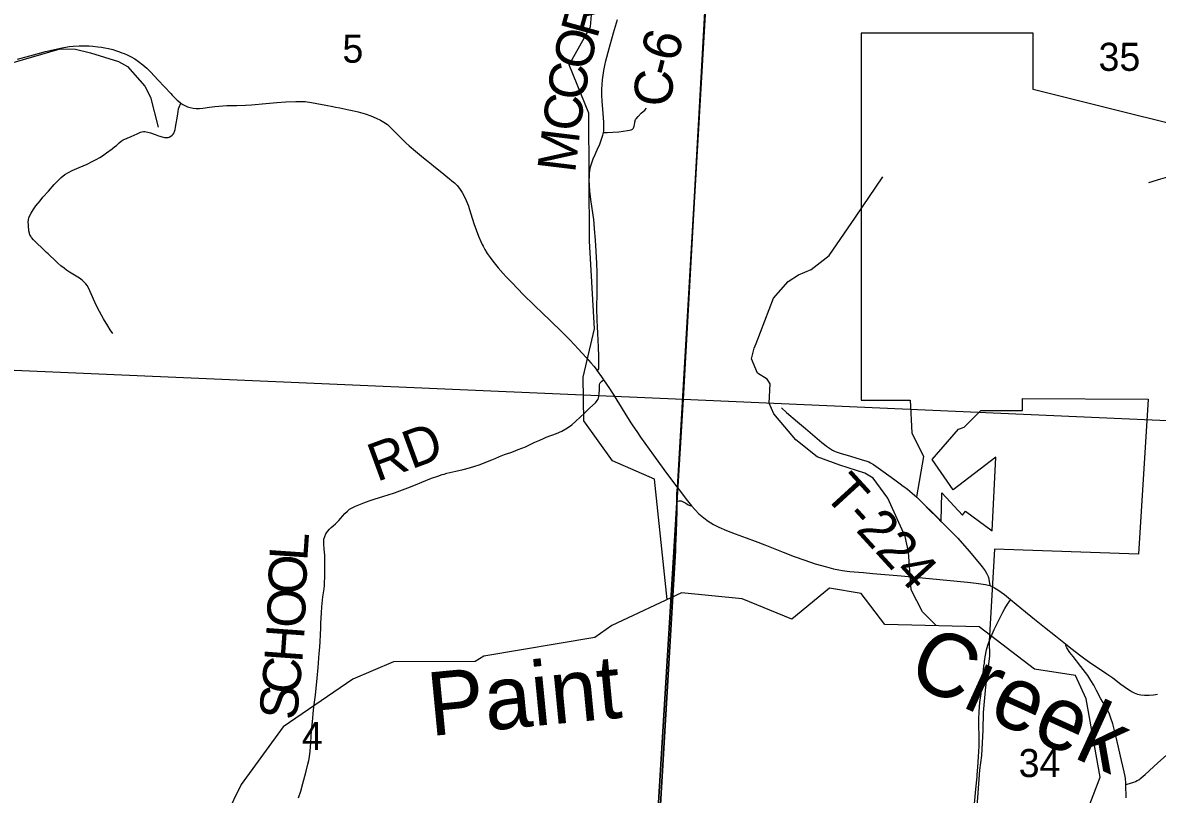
# Model space of a CAD drawing. Extents: x 0 to 34, y 0 to 22.
# Drawn here: x 5.267 to 6.959, y 19.422 to 20.572 of the extents above; entities that cross this region are included whole.
import ezdxf

# ---------------------------------------------------------------- set-up
doc = ezdxf.new("R2010")
doc.units = 0
for name, color, linetype in [('Default', 7, 'Continuous'), ('GM_X_City_Street', 7, 'Continuous'), ('GM_X_County_Road', 7, 'Continuous'), ('GM_X_County_Road_Text', 7, 'Continuous'), ('GM_X_Minor_River', 7, 'Continuous'), ('GM_X_Minor_River_Text', 7, 'Continuous'), ('GM_X_Section', 7, 'Continuous'), ('GM_X_Section_Text', 7, 'Continuous'), ('GM_X_State_Route', 7, 'Continuous'), ('GM_X_Township_Road', 7, 'Continuous'), ('GM_X_Township_Road_Text', 7, 'Continuous')]:
    doc.layers.add(name, color=color, linetype=linetype)

msp = doc.modelspace()

# ---------------------------------------------------------------- linework, layer by layer
at = {"layer": 'Default'}
for points in [[(6.0603, 16.8624), (6.127, 17.9511), (6.1612, 18.4732), (6.1665, 18.5542), (6.1773, 18.7192), (6.1898, 18.9313), (6.195, 19.011), (6.2406, 19.7849), (6.241, 19.7927), (6.2413, 19.8018), (6.2418, 19.8127), (6.2424, 19.8289), (6.2426, 19.8432), (6.2426, 19.8474), (6.2427, 19.8586), (6.2428, 19.8591), (6.2428, 19.8627), (6.2428, 19.867), (6.2428, 19.8705), (6.2431, 19.8748), (6.2438, 19.8792), (6.3032, 20.9), (2.1, 20.9), (2.1, 16.1239)], [(8.9, 20.9), (6.3032, 20.9), (6.2438, 19.8792), (6.2431, 19.8748), (6.2428, 19.8705), (6.2428, 19.867), (6.2428, 19.8627), (6.2428, 19.8591), (6.2427, 19.8586), (6.2426, 19.8474), (6.2426, 19.8432), (6.2424, 19.8289), (6.2418, 19.8127), (6.2413, 19.8018), (6.241, 19.7927), (6.2406, 19.7849), (6.195, 19.011), (6.1898, 18.9313), (6.1773, 18.7192), (6.1665, 18.5542), (6.1612, 18.4732), (6.127, 17.9511), (6.0603, 16.8624)], [(7.1065, 20.3898), (6.7739, 20.4727), (6.7739, 20.5566), (6.5176, 20.5566), (6.5176, 20.0093), (6.5907, 20.0093), (6.5933, 19.9608), (6.6104, 19.9252), (6.6004, 19.8655), (6.6369, 19.8288), (6.6379, 19.8713), (6.6688, 19.8381), (6.6733, 19.8438), (6.7128, 19.8147), (6.7182, 19.9243), (6.6546, 19.8757), (6.6236, 19.9208), (6.663, 19.9661), (6.6711, 19.9691), (6.6961, 19.9941), (6.7582, 19.9941), (6.7582, 20.0121), (6.9455, 20.011), (6.9314, 19.7799), (6.7164, 19.7873), (6.7084, 19.6502), (6.7092, 19.6275), (6.7029, 19.5821), (6.6998, 19.5435), (6.6993, 19.5175), (6.6972, 19.4796), (6.694, 19.4577), (6.6895, 19.3966)]]:
    msp.add_lwpolyline(points, dxfattribs=at)
for points in [[(6.302, 20.9), (5.259, 20.9), (5.2086, 20.056), (6.2522, 20.0112)], [(7.3433, 20.9), (6.302, 20.9), (6.2522, 20.0112), (7.2788, 19.9659)]]:
    msp.add_lwpolyline(points, close=True, dxfattribs=at)
at = {"layer": 'GM_X_City_Street'}
msp.add_lwpolyline([(6.9125, 19.4362), (6.9142, 19.4368), (6.9242, 19.4399), (6.9266, 19.4408), (6.9291, 19.442), (6.9315, 19.4434), (6.935, 19.4462), (6.941, 19.4511), (6.9598, 19.4685), (6.973, 19.4798), (6.9863, 19.4914), (6.9988, 19.5023), (7.0056, 19.5084), (7.0158, 19.5178), (7.0229, 19.5243), (7.0354, 19.5355), (7.0439, 19.5432), (7.0694, 19.5663), (7.0777, 19.5738), (7.0967, 19.5917), (7.1058, 19.6007), (7.1078, 19.6031), (7.1091, 19.6053), (7.1104, 19.6082)], dxfattribs=at)
at = {"layer": 'GM_X_County_Road'}
for points in [[(6.124, 20.0534), (6.1255, 20.0547), (6.1264, 20.0562), (6.1267, 20.0581), (6.1267, 20.0619), (6.1266, 20.0744), (6.1262, 20.0889), (6.1252, 20.1088), (6.1246, 20.1194), (6.1242, 20.1283), (6.1237, 20.147), (6.1238, 20.169), (6.1238, 20.1853), (6.1238, 20.2006), (6.1233, 20.2131), (6.1224, 20.2319), (6.1214, 20.248), (6.1201, 20.2648), (6.1196, 20.2723), (6.1188, 20.279), (6.1152, 20.3054), (6.1133, 20.3209), (6.1125, 20.3306), (6.1122, 20.3374), (6.1124, 20.3425), (6.1127, 20.3473), (6.1132, 20.3515), (6.1137, 20.3547), (6.1143, 20.3575), (6.115, 20.3605), (6.1159, 20.3634), (6.1179, 20.3693), (6.121, 20.3761), (6.1242, 20.3829), (6.1278, 20.3913), (6.1306, 20.3989), (6.1325, 20.4049), (6.1333, 20.4086), (6.1337, 20.4109), (6.1338, 20.4136), (6.1339, 20.4189), (6.1337, 20.4243), (6.1328, 20.4369), (6.1313, 20.4556), (6.1309, 20.4643), (6.1309, 20.4731), (6.1314, 20.4804), (6.1319, 20.4874), (6.1327, 20.4943), (6.1338, 20.5009), (6.1354, 20.5085), (6.1371, 20.5157), (6.1419, 20.5341), (6.1484, 20.5572), (6.1543, 20.5772)], [(6.913, 19.4164), (6.9125, 19.4362), (6.9125, 19.4378), (6.9116, 19.4459), (6.911, 19.4506), (6.91, 19.4551), (6.9056, 19.4721), (6.8992, 19.5002), (6.8953, 19.5167), (6.8927, 19.5267), (6.89, 19.5352), (6.8878, 19.5412), (6.8858, 19.5458), (6.88, 19.5559), (6.875, 19.5642), (6.8685, 19.5766), (6.8645, 19.5845), (6.8603, 19.5914), (6.8555, 19.5986), (6.8522, 19.6031), (6.8452, 19.6122), (6.8338, 19.627), (6.8289, 19.6332), (6.8242, 19.6401), (6.8233, 19.6421), (6.8226, 19.644), (6.8223, 19.6462)]]:
    msp.add_lwpolyline(points, dxfattribs=at)
at = {"layer": 'GM_X_Minor_River'}
for points in [[(6.2282, 19.712), (6.2097, 19.8916), (6.1471, 19.9191), (6.1042, 19.9787), (6.1033, 20.0436), (6.1202, 20.1158), (6.1124, 20.2467), (6.1114, 20.4376), (6.0824, 20.5098), (6.1139, 20.5663), (6.1185, 20.6206)], [(4.8862, 20.5519), (5.0445, 20.4475), (5.0679, 20.4257), (5.0873, 20.4221), (5.126, 20.4256), (5.1626, 20.4393), (5.1909, 20.456), (5.2212, 20.4928), (5.2532, 20.5133), (5.3235, 20.5335), (5.3459, 20.533), (5.3683, 20.5276), (5.4102, 20.5147), (5.4236, 20.5069), (5.4497, 20.4779), (5.4578, 20.4616), (5.4693, 20.4165)], [(6.6293, 19.6732), (6.6091, 19.6937), (6.5924, 19.7268), (6.5883, 19.7834), (6.5834, 19.8059), (6.5576, 19.8632), (6.5356, 19.8929), (6.5231, 19.9004), (6.486, 19.9126), (6.4519, 19.9247), (6.4204, 19.9501), (6.3875, 19.9893), (6.3806, 20.0048), (6.3818, 20.0337), (6.3776, 20.0409), (6.3632, 20.0497), (6.3541, 20.0713), (6.3583, 20.0869), (6.3613, 20.0941), (6.3868, 20.1618), (6.4088, 20.1866), (6.4243, 20.1965), (6.4433, 20.2045), (6.4698, 20.2254), (6.5092, 20.2825), (6.5502, 20.3426)], [(6.8507, 19.3862), (6.8742, 19.4471), (6.8529, 19.5642), (6.8373, 19.5986), (6.7761, 19.6083), (6.6936, 19.6716), (6.5527, 19.6749), (6.5176, 19.7209), (6.4704, 19.7289), (6.4144, 19.6828), (6.34, 19.7133), (6.2495, 19.7219), (6.1458, 19.6736), (6.1206, 19.6555), (5.9551, 19.6275), (5.9419, 19.6198), (5.8204, 19.6194), (5.7596, 19.5931), (5.6558, 19.522), (5.5931, 19.4364), (5.5484, 19.3449)]]:
    msp.add_lwpolyline(points, dxfattribs=at)
at = {"layer": 'GM_X_Section'}
for points in [[(6.2522, 20.0112), (6.1895, 18.9865), (5.1485, 19.0298), (5.159, 19.2125), (5.1842, 19.6356), (5.2086, 20.056)], [(6.2522, 20.0112), (7.2788, 19.9659), (7.2183, 19.0454), (7.2111, 19.0396), (7.2009, 19.0309), (7.1911, 19.0218), (7.1794, 19.0123), (7.1605, 18.9948), (7.1379, 18.9735), (7.1205, 18.9571), (7.1137, 18.9506), (7.1073, 18.9438), (6.1895, 18.9865)]]:
    msp.add_lwpolyline(points, close=True, dxfattribs=at)
at = {"layer": 'GM_X_State_Route'}
for points in [[(5.2595, 20.5179), (5.2834, 20.5247), (5.3014, 20.5294), (5.3129, 20.5321), (5.3238, 20.5345), (5.3366, 20.5368), (5.3429, 20.5376), (5.3514, 20.538), (5.3587, 20.5379), (5.3667, 20.5377), (5.3719, 20.5373), (5.3795, 20.5366), (5.3847, 20.5358), (5.3901, 20.5349), (5.3955, 20.5338), (5.4016, 20.5323), (5.4075, 20.5306), (5.4119, 20.5291), (5.4154, 20.5277), (5.4186, 20.5265), (5.4231, 20.5246), (5.4292, 20.5217), (5.4345, 20.5185), (5.44, 20.5147), (5.4464, 20.5097), (5.4524, 20.5045), (5.4578, 20.4993), (5.4696, 20.4867), (5.479, 20.4767), (5.4884, 20.4669), (5.4905, 20.4646), (5.4979, 20.4569), (5.5021, 20.4532), (5.5034, 20.4522), (5.5063, 20.4502), (5.509, 20.4488), (5.5131, 20.4471), (5.5173, 20.4458), (5.5216, 20.4449), (5.526, 20.4446), (5.5311, 20.4445), (5.5361, 20.4449), (5.5459, 20.4464), (5.5539, 20.4474), (5.572, 20.4487), (5.5869, 20.4491), (5.5996, 20.4494), (5.6084, 20.4499), (5.6301, 20.4519), (5.6462, 20.4533), (5.6598, 20.4543), (5.6746, 20.4549), (5.6826, 20.455), (5.6888, 20.4547), (5.698, 20.4536), (5.7062, 20.4521), (5.7192, 20.4496), (5.7301, 20.4474), (5.7338, 20.4467), (5.7405, 20.4454), (5.7538, 20.4427), (5.7586, 20.4416), (5.7676, 20.4394), (5.7783, 20.4363), (5.7865, 20.4336), (5.7945, 20.4303), (5.8011, 20.427), (5.8059, 20.4243), (5.8113, 20.4204), (5.8153, 20.4166), (5.8192, 20.4127), (5.8231, 20.4087), (5.8262, 20.4057), (5.8306, 20.4013), (5.8386, 20.3934), (5.8437, 20.3889), (5.8532, 20.3809), (5.8652, 20.371), (5.8695, 20.3674), (5.8772, 20.3612), (5.8806, 20.3585), (5.8897, 20.351), (5.9036, 20.3396), (5.9075, 20.3366), (5.9112, 20.3334), (5.9152, 20.3296), (5.9187, 20.3254), (5.9227, 20.3192), (5.9257, 20.3139), (5.9288, 20.3072), (5.9314, 20.3002), (5.9355, 20.2872), (5.9402, 20.2731), (5.9434, 20.2636), (5.947, 20.2543), (5.9505, 20.2463), (5.9525, 20.2418), (5.954, 20.239), (5.9567, 20.2341), (5.9601, 20.2282), (5.9643, 20.222), (5.9697, 20.215), (5.9703, 20.2143)], [(5.9703, 20.2143), (5.9765, 20.2069), (5.9839, 20.1985), (5.9885, 20.1934), (5.9966, 20.1848), (6.0143, 20.1665), (6.0294, 20.1517), (6.0442, 20.1376), (6.0519, 20.1304), (6.0585, 20.1239), (6.0674, 20.1152), (6.0744, 20.1082), (6.0797, 20.1029), (6.0827, 20.0998), (6.09, 20.0922), (6.0958, 20.0858), (6.1076, 20.073), (6.1147, 20.0652), (6.119, 20.06), (6.1224, 20.0556), (6.124, 20.0534), (6.1303, 20.0445), (6.1335, 20.0399), (6.1422, 20.0271), (6.1459, 20.0214), (6.149, 20.0167), (6.1535, 20.0093), (6.16, 19.9988), (6.1668, 19.9877), (6.1704, 19.9819), (6.1734, 19.9772), (6.1771, 19.9714), (6.183, 19.9626), (6.1887, 19.9545), (6.2082, 19.9272), (6.2235, 19.906), (6.244, 19.8787)], [(6.244, 19.8787), (6.2466, 19.8752), (6.2569, 19.8619), (6.2646, 19.8519), (6.2699, 19.8459), (6.2758, 19.84), (6.2828, 19.8341), (6.2895, 19.829), (6.2977, 19.8242), (6.3055, 19.8201), (6.3169, 19.8151), (6.3296, 19.8101), (6.3462, 19.8039), (6.3595, 19.7991), (6.3742, 19.7935), (6.4013, 19.7829), (6.4179, 19.7764), (6.4336, 19.7709), (6.4491, 19.7656), (6.4659, 19.7607), (6.4762, 19.7581), (6.4841, 19.7565), (6.49, 19.7554), (6.4966, 19.7545), (6.5007, 19.7541), (6.507, 19.7535), (6.521, 19.7522), (6.535, 19.751), (6.5774, 19.7474), (6.6194, 19.7437), (6.6762, 19.7382), (6.6891, 19.7367), (6.703, 19.7344), (6.7095, 19.733)], [(6.7095, 19.733), (6.7132, 19.7314), (6.7164, 19.7297), (6.7215, 19.7265), (6.7315, 19.7195), (6.7405, 19.712), (6.7573, 19.6981), (6.7761, 19.6828), (6.7912, 19.6709), (6.8073, 19.6582), (6.8223, 19.6462), (6.8303, 19.6397), (6.8452, 19.6282), (6.8512, 19.6238), (6.8582, 19.6189), (6.8839, 19.6015), (6.8928, 19.5954), (6.9048, 19.5861), (6.9149, 19.5787), (6.9187, 19.5763), (6.9216, 19.5746), (6.9249, 19.5728), (6.9274, 19.5719), (6.9298, 19.571), (6.9323, 19.5704), (6.9346, 19.5699), (6.9402, 19.5693), (6.9471, 19.5693), (6.9536, 19.5699), (6.9595, 19.571)]]:
    msp.add_lwpolyline(points, dxfattribs=at)
at = {"layer": 'GM_X_Township_Road'}
for points in [[(5.4016, 20.1091), (5.3979, 20.1146), (5.3942, 20.1204), (5.3881, 20.1309), (5.3821, 20.1417), (5.3765, 20.1523), (5.3713, 20.1634), (5.3653, 20.177), (5.3635, 20.1803), (5.3617, 20.1828), (5.3588, 20.186), (5.356, 20.1884), (5.3519, 20.1912), (5.3372, 20.2005), (5.3327, 20.2035), (5.329, 20.2061), (5.3245, 20.2096), (5.32, 20.2137), (5.3149, 20.2187), (5.3081, 20.2251), (5.3053, 20.2276), (5.3031, 20.2297), (5.3008, 20.2318), (5.2973, 20.2353), (5.2873, 20.2446), (5.2834, 20.2485), (5.2806, 20.2519), (5.2793, 20.254), (5.2783, 20.2561), (5.2776, 20.2583), (5.2768, 20.2618), (5.2765, 20.2641), (5.2761, 20.2676), (5.2759, 20.2714), (5.2758, 20.2749), (5.2761, 20.2782), (5.2767, 20.2813), (5.2776, 20.2837), (5.28, 20.2886), (5.2828, 20.2932), (5.2871, 20.2991), (5.2933, 20.3068), (5.2976, 20.312), (5.3057, 20.3213), (5.3144, 20.331), (5.3208, 20.3378), (5.3249, 20.3416), (5.3303, 20.3458), (5.3356, 20.3491), (5.3411, 20.3519), (5.3514, 20.3563), (5.3633, 20.3616), (5.3711, 20.3653), (5.3771, 20.3686), (5.3822, 20.3714), (5.3862, 20.374), (5.3924, 20.3782), (5.4008, 20.3845), (5.4047, 20.3876), (5.4071, 20.3895), (5.4111, 20.3933), (5.4144, 20.3958), (5.4173, 20.3975), (5.429, 20.4028), (5.438, 20.4069), (5.443, 20.409), (5.4452, 20.4097), (5.4476, 20.41), (5.4497, 20.4101), (5.4517, 20.4098), (5.4542, 20.4094), (5.4579, 20.4082), (5.4648, 20.4056), (5.4699, 20.4037), (5.4752, 20.4023), (5.4788, 20.4014), (5.4806, 20.4012), (5.4831, 20.4012), (5.4843, 20.4014), (5.486, 20.4019), (5.4882, 20.403), (5.4903, 20.4045), (5.4919, 20.4063), (5.4932, 20.4084), (5.4939, 20.4101), (5.4947, 20.4131), (5.4953, 20.4161), (5.4959, 20.4197), (5.4964, 20.4222), (5.4976, 20.4302), (5.499, 20.44), (5.4999, 20.4439), (5.5009, 20.4465), (5.5034, 20.4522)], [(6.1333, 20.4086), (6.1391, 20.4087), (6.1473, 20.4091), (6.1561, 20.4099), (6.1694, 20.4115), (6.1721, 20.412), (6.1745, 20.4125), (6.1757, 20.413), (6.1767, 20.4137), (6.1776, 20.4146), (6.1783, 20.4156), (6.1788, 20.4168), (6.1793, 20.4182), (6.1797, 20.4202), (6.1803, 20.4241), (6.1805, 20.4255), (6.1808, 20.4267), (6.1813, 20.4279), (6.182, 20.429), (6.1851, 20.4325), (6.1898, 20.4374), (6.195, 20.4422), (6.1978, 20.4448)], [(6.9465, 20.3341), (6.9647, 20.3395), (6.9818, 20.3446), (6.9855, 20.3454), (6.9891, 20.346), (6.9934, 20.3463), (6.9983, 20.346), (7.002, 20.3453), (7.0061, 20.3439), (7.0119, 20.3418), (7.0243, 20.3379), (7.0387, 20.3334), (7.0516, 20.3297), (7.0612, 20.3262), (7.0746, 20.3198), (7.0787, 20.3179), (7.0827, 20.3164), (7.0878, 20.3146), (7.0931, 20.3132), (7.0941, 20.3132)], [(5.8959, 19.8993), (5.9, 19.9005), (5.9132, 19.9037), (5.9241, 19.9063), (5.9338, 19.9086), (5.9415, 19.9109), (5.948, 19.9131), (5.9543, 19.9156), (5.9606, 19.9181), (5.9669, 19.9206), (5.972, 19.9227), (5.9784, 19.9252), (5.9858, 19.9283), (5.9905, 19.9299), (5.9951, 19.9316), (5.9992, 19.9331), (6.0062, 19.9357), (6.0171, 19.9401), (6.0311, 19.9467), (6.0384, 19.95), (6.044, 19.9525), (6.0481, 19.9542), (6.0632, 19.9598), (6.0712, 19.9632), (6.0772, 19.9665), (6.0814, 19.9691), (6.0863, 19.9729), (6.0924, 19.9782), (6.105, 19.9902), (6.1131, 19.9979), (6.1213, 20.0056), (6.1241, 20.0089), (6.1254, 20.011), (6.126, 20.0127), (6.1266, 20.0151), (6.1271, 20.02), (6.1273, 20.0243), (6.1275, 20.0274), (6.1276, 20.0324), (6.1279, 20.0341), (6.1287, 20.0355), (6.1311, 20.0377), (6.1335, 20.0399)], [(6.3991, 19.998), (6.4064, 19.9913), (6.4225, 19.9773), (6.4346, 19.9671), (6.4485, 19.9551), (6.4592, 19.9464), (6.4629, 19.9433), (6.466, 19.941), (6.4691, 19.9388), (6.4721, 19.9368), (6.4748, 19.9351), (6.4777, 19.9335), (6.4804, 19.9325), (6.4862, 19.9306), (6.5015, 19.9257), (6.5176, 19.921), (6.5263, 19.9184), (6.529, 19.9175), (6.5314, 19.9161), (6.5361, 19.9133), (6.5498, 19.9037), (6.5588, 19.8972), (6.5678, 19.8906), (6.5757, 19.8848), (6.5803, 19.8814), (6.5811, 19.8808)], [(5.6789, 19.4162), (5.682, 19.4263), (5.6852, 19.4377), (5.6879, 19.4485), (5.6899, 19.4563), (5.6927, 19.4668), (5.6939, 19.4722), (5.6949, 19.4777), (5.6959, 19.4862), (5.697, 19.499), (5.6981, 19.5167), (5.6993, 19.5298), (5.7003, 19.5417), (5.7014, 19.552), (5.7039, 19.5696), (5.7065, 19.5949), (5.708, 19.6109), (5.7097, 19.6317), (5.7104, 19.641), (5.7109, 19.6496), (5.7115, 19.6595), (5.7116, 19.6626), (5.7118, 19.6669), (5.7119, 19.6688), (5.7122, 19.6769), (5.7128, 19.6924), (5.7133, 19.7011), (5.7151, 19.7159), (5.7161, 19.722), (5.7169, 19.7282), (5.7173, 19.7331), (5.7174, 19.7362), (5.7176, 19.7393), (5.7177, 19.7436), (5.7179, 19.7492), (5.7181, 19.7591), (5.7181, 19.7701), (5.7177, 19.7781), (5.717, 19.7873), (5.7164, 19.7953), (5.7164, 19.7996), (5.7166, 19.8021), (5.7177, 19.8062), (5.7194, 19.8102), (5.7218, 19.8138), (5.7247, 19.817), (5.7274, 19.8195), (5.7302, 19.8219), (5.7339, 19.8252), (5.7388, 19.8299), (5.742, 19.8336), (5.7444, 19.8364), (5.7476, 19.8402), (5.7515, 19.8441), (5.7549, 19.8467), (5.7586, 19.8489), (5.7636, 19.8513), (5.7762, 19.8563), (5.7841, 19.8593), (5.7928, 19.8621), (5.7981, 19.8637), (5.8058, 19.8661), (5.8123, 19.8682), (5.8216, 19.8713), (5.8419, 19.8787), (5.8529, 19.883), (5.8626, 19.887), (5.877, 19.8929), (5.8863, 19.8963), (5.8928, 19.8984), (5.8959, 19.8993)], [(6.5811, 19.8808), (6.5866, 19.8768), (6.5937, 19.8709), (6.6006, 19.8649), (6.6013, 19.8643)], [(6.2408, 19.7843), (6.2413, 19.7921), (6.2415, 19.8012), (6.242, 19.8122), (6.2426, 19.8284), (6.2428, 19.8427), (6.2428, 19.8469), (6.243, 19.8581), (6.243, 19.8622), (6.243, 19.8665), (6.2431, 19.87), (6.2433, 19.8742), (6.244, 19.8787)], [(6.6013, 19.8643), (6.6104, 19.8549), (6.618, 19.8471), (6.6319, 19.8334), (6.6371, 19.8282), (6.6378, 19.8275)], [(6.243, 19.8581), (6.2462, 19.8592), (6.247, 19.8593), (6.2483, 19.8594), (6.2492, 19.8592), (6.2502, 19.859), (6.2513, 19.8585), (6.2524, 19.8579), (6.254, 19.8568), (6.256, 19.8556), (6.2578, 19.8546), (6.2599, 19.8534), (6.2622, 19.8525), (6.2646, 19.8519)], [(6.6378, 19.8275), (6.6506, 19.8151), (6.6618, 19.8036), (6.6788, 19.7844), (6.6942, 19.7659), (6.698, 19.7607), (6.7023, 19.7548), (6.7044, 19.7514), (6.7069, 19.7466), (6.7077, 19.7449), (6.7081, 19.7427), (6.7095, 19.733)], [(6.7086, 19.6497), (6.7113, 19.6572), (6.7158, 19.6673), (6.7189, 19.6736), (6.7287, 19.6931), (6.7319, 19.6988), (6.736, 19.7053), (6.7394, 19.7103), (6.7405, 19.712)], [(6.7016, 19.62), (6.702, 19.6228), (6.7025, 19.6265), (6.7046, 19.6369), (6.7066, 19.6439), (6.7086, 19.6497)], [(6.6996, 19.6004), (6.6998, 19.6024), (6.7008, 19.6129), (6.7013, 19.6172), (6.7016, 19.62)], [(6.6908, 19.4505), (6.6916, 19.4623), (6.6927, 19.4777), (6.6937, 19.4936), (6.6938, 19.503), (6.6934, 19.5106), (6.6931, 19.5218), (6.6929, 19.5331), (6.6936, 19.5449), (6.6948, 19.5586), (6.6965, 19.5721), (6.6984, 19.5883), (6.6996, 19.6004)], [(6.685, 19.3902), (6.6852, 19.3922), (6.6859, 19.4017), (6.6877, 19.4184), (6.6887, 19.4294), (6.6906, 19.4475), (6.6908, 19.4505)]]:
    msp.add_lwpolyline(points, dxfattribs=at)

# ---------------------------------------------------------------- texts
at = {"layer": 'GM_X_County_Road_Text'}
for s, rotation, p in [('R', 74.4803, (6.1237, 20.5472)), ('O', 76.2067, (6.1119, 20.499)), ('6', 75.1444, (6.243, 20.512)), ('C', 80.5511, (6.1045, 20.4541)), ('-', 75.8093, (6.2374, 20.4898)), ('C', 86.4285, (6.2349, 20.4463)), ('C', 82.4611, (6.0984, 20.4084)), ('M', 83.0926, (6.091, 20.3473))]:
    msp.add_text(s, height=0.0568, rotation=rotation, dxfattribs=at).set_placement(p)
at = {"layer": 'GM_X_Minor_River_Text'}
for s, height, rotation, p in [('Creek', 0.09469, 335.5162, (6.5828, 19.5908)), ('Paint', 0.0947, 5.5114, (5.8756, 19.5084))]:
    msp.add_text(s, height=height, rotation=rotation, dxfattribs=at).set_placement(p)
at = {"layer": 'GM_X_Section_Text'}
for s, height, p in [('5', 0.0419, (5.7441, 20.5128)), ('35', 0.04186, (6.8716, 20.5006)), ('4', 0.0419, (5.6837, 19.4876)), ('34', 0.04186, (6.7525, 19.4473))]:
    msp.add_text(s, height=height, rotation=0, dxfattribs=at).set_placement(p)
at = {"layer": 'GM_X_Township_Road_Text'}
for s, height, rotation, p in [('RD', 0.05682, 20.1431, (5.7955, 19.8873)), ('T-224', 0.05682, 312.4626, (6.46, 19.8681)), ('L', 0.0568, 86.0542, (5.6916, 19.7687)), ('O', 0.0568, 88.0202, (5.6899, 19.7193)), ('O', 0.0568, 87.6881, (5.6879, 19.669)), ('H', 0.0568, 85.8751, (5.6842, 19.6171)), ('C', 0.0568, 84.6231, (5.6797, 19.5693)), ('S', 0.0568, 84.5561, (5.6761, 19.5311))]:
    msp.add_text(s, height=height, rotation=rotation, dxfattribs=at).set_placement(p)

doc.saveas('drawing.dxf')
